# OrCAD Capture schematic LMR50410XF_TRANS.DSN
size D; title: LMR50410XF SIMPLE SWITCHER® 4-V to 36-V, 1-A Buck; rev: 1.0; note: Datasheet: SLUSDW3A      EVM:SLUUCF0; note: Synchronous Step Down Converter; note: Converter in SOT-23-6 package
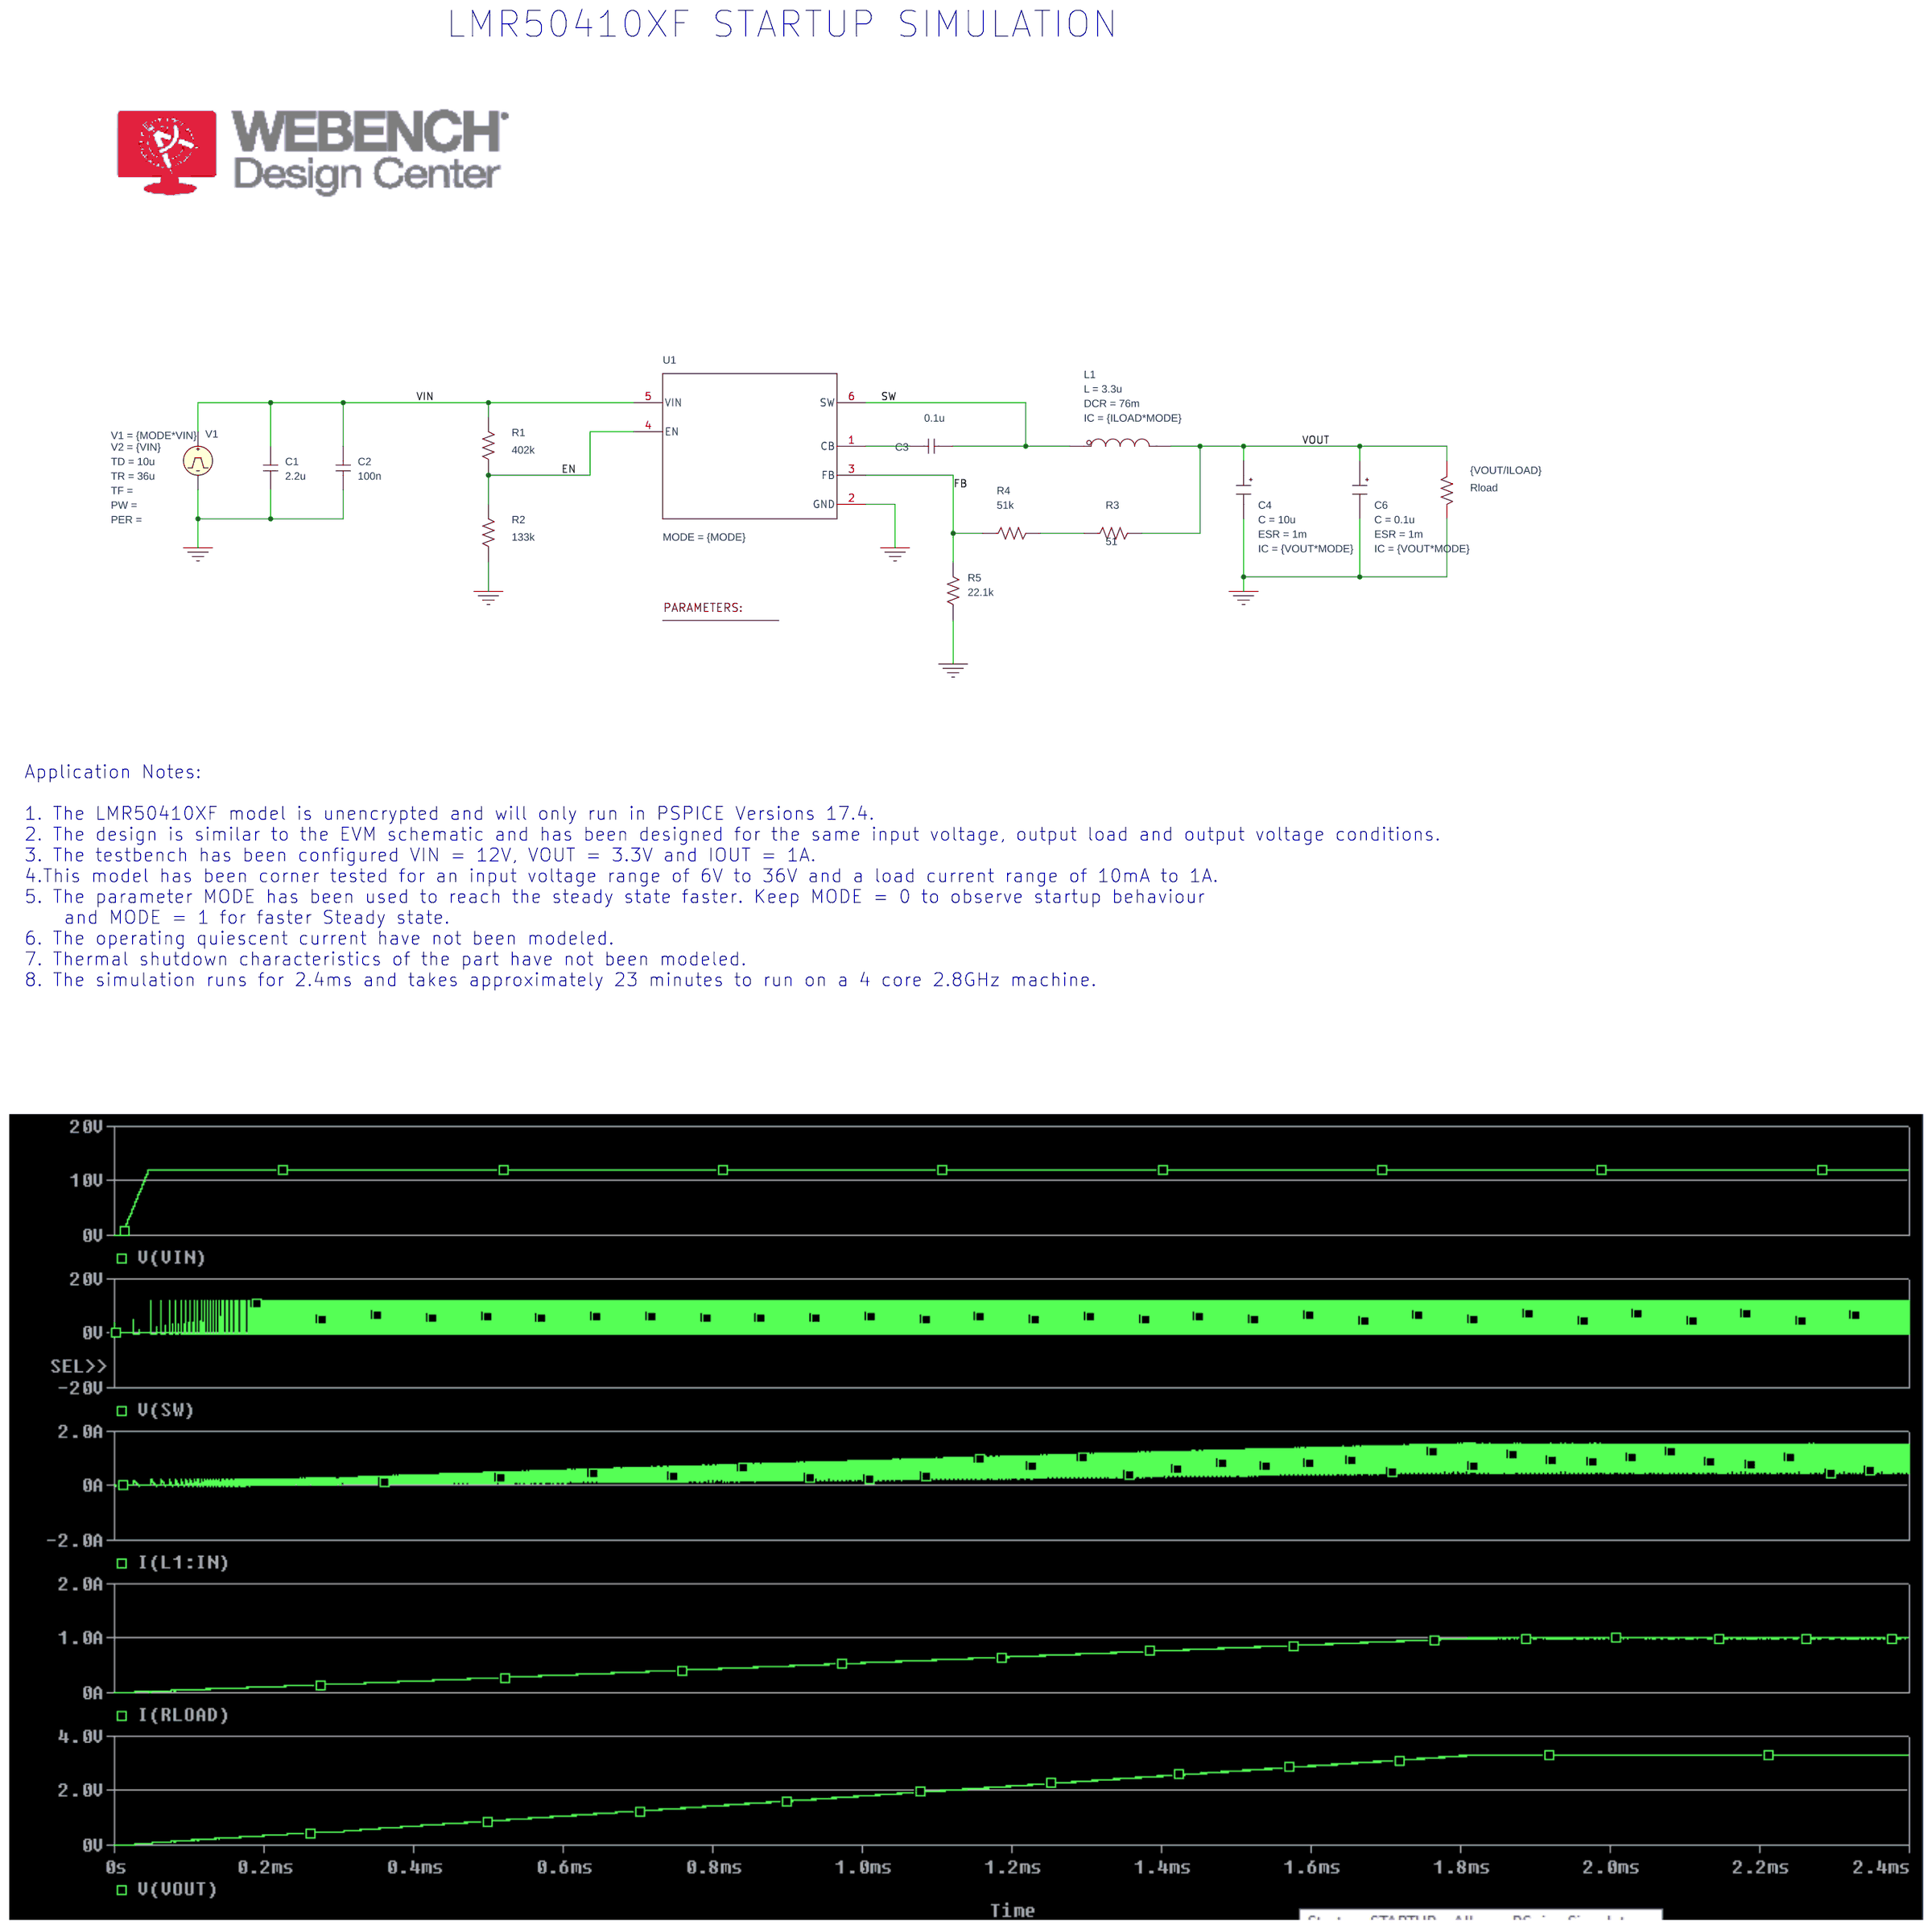
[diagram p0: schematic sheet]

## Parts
1  PARAM
C1  2.2u  [RAD/CK05]
C2  100n  [RAD/CK05]
C3  0.1u  [RAD/CK05]
C4  CESR
C6  CESR
L1  LDCR
R1  402k  [AX/RC05]
R2  133k  [AX/RC05]
R3  51  [AX/RC05]
R4  51k  [RC05]
R5  22.1k  [RC05]
Rload  {VOUT/ILOAD}  [AX/RC05]
U1  Value  [DBV0006A-IPC_A]
V1  VPULSE

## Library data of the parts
1 = PARAM: MODE: 0; VIN: 12; VOUT: 3.3
C1 C2 = C
C3 = C: IC: -3.3
C4 = CESR_0: C: 10u; ESR: 1m; IC: {VOUT*MODE}; PSpiceTemplate: X^@REFDES %IN %OUT @MODEL PARAMS:  ?C|C=@C||C=100u|  ?ESR|ESR=@ESR||ESR=0.01| ?X|X=@X||X=2|  ?IC|IC=@IC||IC=2|; X: 1
C6 = CESR_0: C: 0.1u; ESR: 1m; IC: {VOUT*MODE}; PSpiceTemplate: X^@REFDES %IN %OUT @MODEL PARAMS:  ?C|C=@C||C=100u|  ?ESR|ESR=@ESR||ESR=0.01| ?X|X=@X||X=2|  ?IC|IC=@IC||IC=2|; X: 1
L1 = LDCR_0: DCR: 76m; IC: {ILOAD*MODE}; L: 3.3u; PSpiceTemplate: X^@REFDES %IN %OUT @MODEL PARAMS:  ?L|L=@L||L=1u|  ?DCR|DCR=@DCR||DCR=0.01| ?IC|IC=@IC||IC=0|
R1-R5 Rload = R
U1 = LMR50410XFDBV_TRANS: MODE: {MODE}
V1 = VPULSE: TD: 10u; TR: 36u; V1: {MODE*VIN}; V2: {VIN}

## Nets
VIN: C1.2 C2.2 R1.2 U1.5(VIN) V1.1(+)
0: C1.1 C2.1 C4.3(OUT) C6.3(OUT) R2.1 R5.1 Rload.2 U1.2(GND) V1.2(-)
EN: R1.1 R2.2 U1.4(EN)
FB: R4.1 R5.2 U1.3(FB)
SW: C3.2 L1.1(IN) U1.6(SW)
VOUT: C4.1(IN) C6.1(IN) L1.3(OUT) R3.2 Rload.1
N16772941: R3.1 R4.2
N16773288: C3.1 U1.1(CB)

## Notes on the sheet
- LMR50410XF STARTUP SIMULATION
- Application Notes:
  1. The LMR50410XF model is unencrypted and will only run in PSPICE Versions 17.4.
  2. The design is similar to the EVM schematic and has been designed for the same input voltage, output load and output voltage conditions.
  3. The testbench has been configured VIN = 12V, VOUT = 3.3V and IOUT = 1A.
  4.This model has been corner tested for an input voltage range of 6V to 36V and a load current range of 10mA to 1A.
  5. The parameter MODE has been used to reach the steady state faster. Keep MODE = 0 to observe startup behaviour
      and MODE = 1 for faster Steady state.
  6. The operating quiescent current have not been modeled.
  7. Thermal shutdown characteristics of the part have not been modeled.
  8. The simulation runs for 2.4ms and takes approximately 23 minutes to run on a 4 core 2.8GHz machine.
